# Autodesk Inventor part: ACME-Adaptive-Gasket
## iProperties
Company: Autodesk, Inc.
Shininess: 64.0
Length Units: 11269
Angle Units: 11279
Time Units: 11290
Mass Units: 11283
Length Display Precision: 3
Angle Display Precision: 2
Compacted: True
Part Number: ACME-Adaptive-Gasket
Document SubType Name: Modeling
Created: 2003-12
Catalog Web Link: www.autodesk.com
Vendor: Autodesk, Inc.
Designer: Administrator
Manufacturer: Standard
Standards Organization: Custom
Density: 1 g/cm^3
Mass: 0.159301 g
Surface Area: 5.49831 cm^2
Volume: 0.159301 cm^3
Density: 0.0
Volumn: 0.0
Area: 0.0
PropertySet Name: Model Information
Control State: 0
Master: False
Checked Out: False
Author: Administrator
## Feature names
1. Extrusion1
